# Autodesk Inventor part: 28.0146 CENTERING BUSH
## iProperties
Created: 2007-06
Part Number: 28.0146 CENTERING BUSH
Material: Aluminum-6061
Document SubType Name: Modeling
Designer: Andy Moles
Density: 2.71 g/cm^3
Author: Andy Moles
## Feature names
1. Extrusion1
2. Extrusion2
3. Chamfer1
